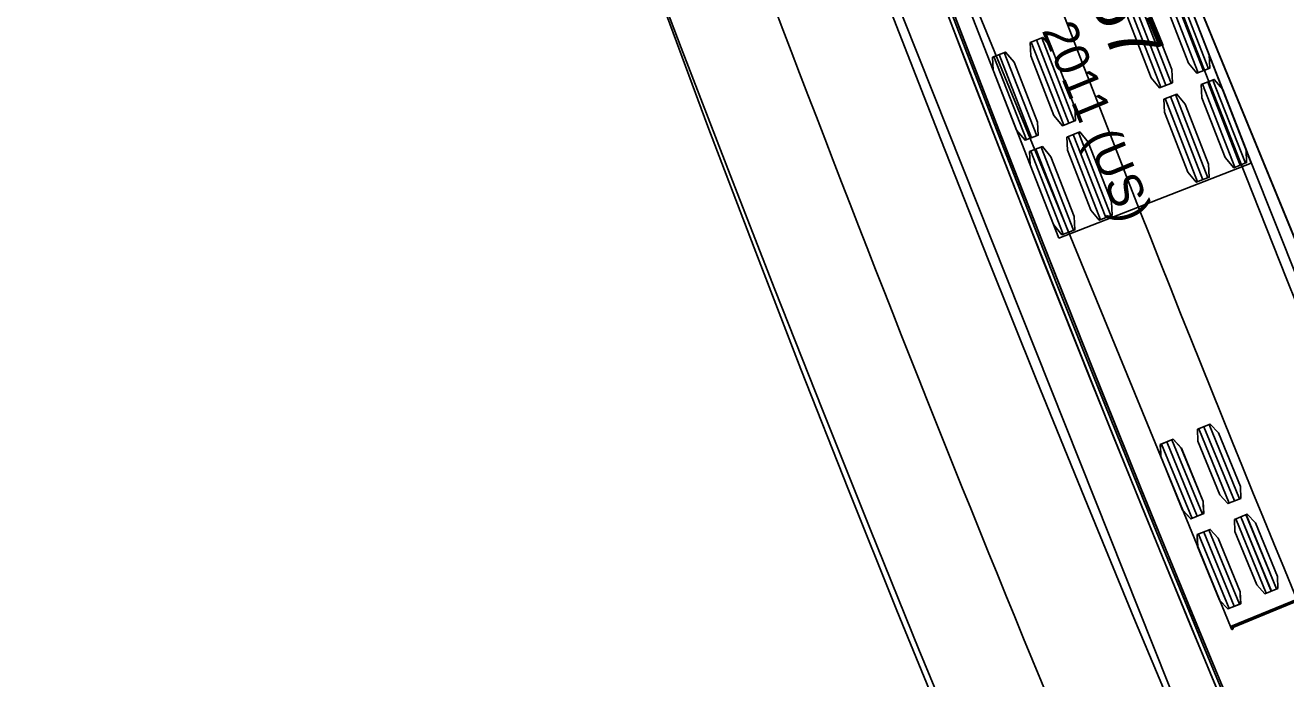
# Model space of a CAD drawing. Extents: x 1639988 to 1641860, y 841974 to 844187.
# Drawn here: x 1640169.8 to 1640221.6, y 844086 to 844112.9 of the extents above; entities that cross this region are included whole.
import ezdxf

# ---------------------------------------------------------------- set-up
doc = ezdxf.new("R2010")
doc.units = 0
for name, color, linetype in [('Scratch_Level_1', 7, 'Continuous'), ('Scratch_Level_2', 7, 'Continuous'), ('Scratch_Level_3', 7, 'Continuous'), ('Scratch_Level_4', 7, 'Continuous'), ('Scratch_Level_5', 7, 'Continuous'), ('Scratch_Level_6', 7, 'Continuous')]:
    doc.layers.add(name, color=color, linetype=linetype)

msp = doc.modelspace()

# ---------------------------------------------------------------- linework, layer by layer
at = {"layer": 'Scratch_Level_1'}
for p, q in [((1640220.202, 844107.217), (1640204.762, 844146.813)), ((1640196.843, 844143.725), (1640212.283, 844104.129)), ((1640216.685, 844114.343), (1640218.017, 844110.927)), ((1640216.899, 844114.426), (1640218.231, 844111.01)), ((1640217.112, 844114.509), (1640218.444, 844111.093)), ((1640215.148, 844113.744), (1640216.48, 844110.327)), ((1640215.361, 844113.827), (1640216.694, 844110.411)), ((1640215.575, 844113.91), (1640216.907, 844110.494)), ((1640211.157, 844112.187), (1640212.489, 844108.771)), ((1640211.371, 844112.271), (1640212.703, 844108.855)), ((1640211.584, 844112.354), (1640212.916, 844108.938)), ((1640209.62, 844111.588), (1640210.952, 844108.172)), ((1640209.834, 844111.671), (1640211.166, 844108.255)), ((1640210.047, 844111.755), (1640211.379, 844108.338)), ((1640218.199, 844110.461), (1640219.531, 844107.045)), ((1640218.412, 844110.544), (1640219.744, 844107.128)), ((1640218.626, 844110.627), (1640219.958, 844107.211)), ((1640216.875, 844109.945), (1640218.207, 844106.529)), ((1640217.089, 844110.028), (1640218.421, 844106.612)), ((1640216.662, 844109.862), (1640217.994, 844106.445)), ((1640212.884, 844108.389), (1640214.217, 844104.973)), ((1640213.098, 844108.472), (1640214.43, 844105.056)), ((1640211.347, 844107.789), (1640212.679, 844104.373)), ((1640211.561, 844107.873), (1640212.893, 844104.456)), ((1640212.671, 844108.305), (1640214.003, 844104.889)), ((1640211.134, 844107.706), (1640212.466, 844104.29)), ((1640212.283, 844104.129), (1640220.202, 844107.217))]:
    msp.add_line(p, q, dxfattribs=at)
for points in [[(1640240.487, 843983.993), (1640239.855, 843986.609), (1640227.577, 844027.488), (1640224.497, 844037.651), (1640222.927, 844042.709), (1640221.325, 844047.747), (1640219.681, 844052.761), (1640217.992, 844057.753), (1640216.257, 844062.717), (1640214.476, 844067.667), (1640212.652, 844072.609), (1640208.555, 844082.348), (1640206.537, 844087.24), (1640204.541, 844092.149), (1640202.565, 844097.075), (1640200.611, 844102.018), (1640198.676, 844106.976), (1640196.761, 844111.949), (1640192.983, 844121.925), (1640185.677, 844141.598), (1640169.789, 844184.508), (1640177.76, 844187.459), (1640177.815, 844187.311), (1640177.815, 844187.311)], [(1640177.815, 844187.311), (1640188.919, 844157.376), (1640192.648, 844147.427), (1640196.411, 844137.497), (1640200.22, 844127.592), (1640204.089, 844117.705), (1640228.263, 844057.033)], [(1640200.563, 844158.427), (1640204.547, 844146.924), (1640204.762, 844146.813), (1640220.203, 844107.235), (1640222.166, 844102.297), (1640224.155, 844097.371), (1640226.171, 844092.456), (1640228.214, 844087.553), (1640230.284, 844082.66)], [(1640220.307, 844082.415), (1640218.24, 844087.364), (1640216.2, 844092.323), (1640214.186, 844097.294), (1640212.199, 844102.274), (1640210.121, 844107.569), (1640208.206, 844112.529), (1640206.319, 844117.491), (1640204.459, 844122.464), (1640202.625, 844127.447), (1640200.818, 844132.44), (1640199.024, 844137.479), (1640196.843, 844143.725), (1640197.043, 844143.873), (1640195.321, 844148.9)]]:
    msp.add_lwpolyline(points, dxfattribs=at)
for points in [[(1640216.632, 844114.322), (1640217.165, 844114.53), (1640217.512, 844114.114), (1640218.471, 844111.655), (1640218.497, 844111.114), (1640217.964, 844110.906), (1640217.617, 844111.322), (1640216.658, 844113.781)], [(1640215.095, 844113.723), (1640215.628, 844113.931), (1640215.975, 844113.515), (1640216.934, 844111.055), (1640216.96, 844110.515), (1640216.427, 844110.307), (1640216.08, 844110.722), (1640215.121, 844113.182)], [(1640211.104, 844112.167), (1640211.637, 844112.375), (1640211.984, 844111.959), (1640212.943, 844109.499), (1640212.969, 844108.958), (1640212.436, 844108.751), (1640212.089, 844109.166), (1640211.13, 844111.626)], [(1640209.567, 844111.567), (1640210.1, 844111.775), (1640210.447, 844111.36), (1640211.406, 844108.9), (1640211.432, 844108.359), (1640210.899, 844108.151), (1640210.552, 844108.567), (1640209.593, 844111.026)], [(1640218.146, 844110.44), (1640218.679, 844110.648), (1640219.026, 844110.232), (1640219.985, 844107.773), (1640220.011, 844107.232), (1640219.478, 844107.024), (1640219.131, 844107.44), (1640218.172, 844109.899)], [(1640216.609, 844109.841), (1640217.142, 844110.049), (1640217.489, 844109.633), (1640218.448, 844107.173), (1640218.474, 844106.633), (1640217.941, 844106.425), (1640217.594, 844106.84), (1640216.635, 844109.3)], [(1640212.618, 844108.285), (1640213.151, 844108.493), (1640213.498, 844108.077), (1640214.457, 844105.617), (1640214.483, 844105.076), (1640213.95, 844104.869), (1640213.603, 844105.284), (1640212.644, 844107.744)], [(1640211.081, 844107.685), (1640211.614, 844107.893), (1640211.961, 844107.478), (1640212.92, 844105.018), (1640212.946, 844104.477), (1640212.413, 844104.269), (1640212.066, 844104.685), (1640211.107, 844107.145)]]:
    msp.add_lwpolyline(points, close=True, dxfattribs=at)
for radius, start, end in [(994, 198.505393, 206.873019), (1005, 200.317507, 203.824551)]:
    msp.add_arc((1641140.378, 844469.766), radius, start, end, dxfattribs=at)
at = {"layer": 'Scratch_Level_2'}
for p, q in [((1640218.252, 844096.387), (1640219.507, 844093.335)), ((1640218.464, 844096.474), (1640219.719, 844093.422)), ((1640218.04, 844096.3), (1640219.295, 844093.248)), ((1640216.514, 844095.673), (1640217.768, 844092.62)), ((1640216.726, 844095.76), (1640217.98, 844092.708)), ((1640216.938, 844095.847), (1640218.192, 844092.795)), ((1640219.985, 844092.774), (1640221.239, 844089.722)), ((1640219.561, 844092.6), (1640220.815, 844089.548)), ((1640219.773, 844092.687), (1640221.027, 844089.635)), ((1640218.034, 844091.973), (1640219.289, 844088.921)), ((1640218.246, 844092.06), (1640219.501, 844089.008)), ((1640218.458, 844092.147), (1640219.713, 844089.095)), ((1640227.208, 844091.408), (1640219.346, 844088.178))]:
    msp.add_line(p, q, dxfattribs=at)
for points in [[(1640240.487, 843983.993), (1640239.855, 843986.609), (1640227.577, 844027.488), (1640224.497, 844037.651), (1640222.927, 844042.709), (1640221.325, 844047.747), (1640219.681, 844052.761), (1640217.992, 844057.753), (1640216.257, 844062.717), (1640214.476, 844067.667), (1640212.652, 844072.609), (1640208.555, 844082.348), (1640206.537, 844087.24), (1640204.541, 844092.149), (1640202.565, 844097.075), (1640200.611, 844102.018), (1640198.676, 844106.976), (1640196.761, 844111.949), (1640192.983, 844121.925), (1640185.677, 844141.598), (1640169.789, 844184.508), (1640177.76, 844187.459), (1640177.811, 844187.321), (1640177.811, 844187.321)], [(1640177.811, 844187.321), (1640188.919, 844157.376), (1640192.648, 844147.427), (1640196.411, 844137.497), (1640200.22, 844127.592), (1640204.089, 844117.705), (1640228.263, 844057.033)], [(1640220.38, 844082.445), (1640218.314, 844087.392), (1640216.154, 844092.648), (1640214.158, 844097.58), (1640212.19, 844102.516), (1640210.249, 844107.464), (1640208.334, 844112.422), (1640206.445, 844117.391), (1640204.582, 844122.37), (1640202.745, 844127.361), (1640200.909, 844132.432), (1640199.257, 844137.07), (1640199.32, 844137.222), (1640197.553, 844142.266), (1640195.83, 844147.27), (1640194.126, 844152.304), (1640192.663, 844156.699), (1640200.197, 844159.388), (1640205.316, 844145.036), (1640206.939, 844140.402), (1640207.119, 844140.301), (1640227.327, 844091.148), (1640229.381, 844086.251), (1640231.462, 844081.368)], [(1640227.214, 844091.335), (1640227.234, 844091.343), (1640227.208, 844091.408), (1640225.054, 844096.65), (1640207.119, 844140.301), (1640203.188, 844138.686), (1640199.257, 844137.07), (1640217.192, 844093.42), (1640219.347, 844088.178), (1640219.374, 844088.113), (1640219.394, 844088.121)], [(1640219.416, 844088.13), (1640219.417, 844088.131), (1640222.779, 844089.512), (1640222.813, 844089.526), (1640222.839, 844089.461), (1640222.841, 844089.461), (1640223.088, 844089.563)]]:
    msp.add_lwpolyline(points, dxfattribs=at)
for points in [[(1640217.988, 844096.278), (1640218.517, 844096.496), (1640218.852, 844096.134), (1640219.755, 844093.936), (1640219.771, 844093.443), (1640219.242, 844093.226), (1640218.907, 844093.588), (1640218.004, 844095.785)], [(1640216.462, 844095.651), (1640216.991, 844095.869), (1640217.326, 844095.507), (1640218.229, 844093.309), (1640218.245, 844092.816), (1640217.716, 844092.599), (1640217.381, 844092.961), (1640216.478, 844095.158)], [(1640219.508, 844092.578), (1640220.037, 844092.796), (1640220.372, 844092.434), (1640221.275, 844090.236), (1640221.291, 844089.743), (1640220.762, 844089.526), (1640220.427, 844089.888), (1640219.524, 844092.086)], [(1640217.982, 844091.951), (1640218.511, 844092.169), (1640218.846, 844091.807), (1640219.749, 844089.609), (1640219.765, 844089.116), (1640219.236, 844088.899), (1640218.901, 844089.261), (1640217.998, 844091.459)]]:
    msp.add_lwpolyline(points, close=True, dxfattribs=at)
msp.add_circle((1640219.418, 844088.094), 0.0266, dxfattribs=at)
for centre, radius, start, end in [((1641140.378, 844469.766), 994, 198.505393, 206.873019), ((1641140.378, 844469.766), 1005, 200.317507, 203.824551), ((1640219.418, 844088.094), 0.0363, 131.4145, 92.5759)]:
    msp.add_arc(centre, radius, start, end, dxfattribs=at)
at = {"layer": 'Scratch_Level_3'}
for p, q in [((1640218.251, 844096.386), (1640219.505, 844093.334)), ((1640218.463, 844096.474), (1640219.717, 844093.421)), ((1640218.039, 844096.299), (1640219.293, 844093.247)), ((1640216.513, 844095.672), (1640217.767, 844092.62)), ((1640216.725, 844095.759), (1640217.979, 844092.707)), ((1640216.936, 844095.847), (1640218.191, 844092.794)), ((1640219.983, 844092.774), (1640221.237, 844089.721)), ((1640219.559, 844092.599), (1640220.813, 844089.547)), ((1640219.771, 844092.687), (1640221.025, 844089.634)), ((1640218.033, 844091.972), (1640219.287, 844088.92)), ((1640218.245, 844092.059), (1640219.499, 844089.007)), ((1640218.457, 844092.147), (1640219.711, 844089.094)), ((1640227.206, 844091.407), (1640219.344, 844088.177))]:
    msp.add_line(p, q, dxfattribs=at)
for points in [[(1640240.487, 843983.993), (1640239.855, 843986.609), (1640227.577, 844027.488), (1640224.497, 844037.651), (1640222.927, 844042.709), (1640221.325, 844047.747), (1640219.681, 844052.761), (1640217.992, 844057.753), (1640216.257, 844062.717), (1640214.476, 844067.667), (1640212.652, 844072.609), (1640208.555, 844082.348), (1640206.537, 844087.24), (1640204.541, 844092.149), (1640202.565, 844097.075), (1640200.611, 844102.018), (1640198.676, 844106.976), (1640196.761, 844111.949), (1640192.983, 844121.925), (1640185.677, 844141.598), (1640169.789, 844184.508), (1640177.76, 844187.459), (1640177.809, 844187.326), (1640177.809, 844187.326)], [(1640177.809, 844187.326), (1640188.919, 844157.376), (1640192.648, 844147.427), (1640196.411, 844137.497), (1640200.22, 844127.592), (1640204.089, 844117.705), (1640228.263, 844057.033)], [(1640219.861, 844083.681), (1640217.802, 844088.63), (1640215.645, 844093.899), (1640213.642, 844098.867), (1640211.667, 844103.843), (1640209.719, 844108.829), (1640207.797, 844113.826), (1640205.902, 844118.835), (1640204.033, 844123.854), (1640202.184, 844128.901), (1640199.257, 844137.071), (1640199.32, 844137.222), (1640197.553, 844142.266), (1640195.83, 844147.27), (1640194.126, 844152.304), (1640192.663, 844156.699), (1640200.197, 844159.388), (1640205.316, 844145.036), (1640206.939, 844140.403), (1640207.119, 844140.301), (1640227.452, 844090.84), (1640229.508, 844085.945)], [(1640227.213, 844091.334), (1640227.232, 844091.342), (1640227.206, 844091.407), (1640225.053, 844096.649), (1640207.119, 844140.301), (1640203.188, 844138.686), (1640199.257, 844137.071), (1640217.19, 844093.419), (1640219.345, 844088.178), (1640219.372, 844088.112), (1640219.392, 844088.12)], [(1640219.414, 844088.129), (1640219.415, 844088.13), (1640222.778, 844089.512), (1640222.811, 844089.525), (1640222.837, 844089.46), (1640222.839, 844089.46), (1640223.086, 844089.562)]]:
    msp.add_lwpolyline(points, dxfattribs=at)
for points in [[(1640217.986, 844096.278), (1640218.515, 844096.495), (1640218.85, 844096.133), (1640219.753, 844093.936), (1640219.769, 844093.443), (1640219.24, 844093.225), (1640218.905, 844093.587), (1640218.002, 844095.785)], [(1640216.46, 844095.651), (1640216.989, 844095.868), (1640217.324, 844095.506), (1640218.227, 844093.308), (1640218.243, 844092.816), (1640217.714, 844092.598), (1640217.379, 844092.96), (1640216.476, 844095.158)], [(1640219.506, 844092.578), (1640220.035, 844092.795), (1640220.37, 844092.433), (1640221.273, 844090.236), (1640221.289, 844089.743), (1640220.76, 844089.525), (1640220.425, 844089.887), (1640219.522, 844092.085)], [(1640217.98, 844091.951), (1640218.509, 844092.168), (1640218.844, 844091.806), (1640219.747, 844089.609), (1640219.763, 844089.116), (1640219.234, 844088.898), (1640218.899, 844089.26), (1640217.996, 844091.458)]]:
    msp.add_lwpolyline(points, close=True, dxfattribs=at)
msp.add_circle((1640219.416, 844088.093), 0.0266, dxfattribs=at)
for centre, radius, start, end in [((1641140.378, 844469.766), 994, 198.505393, 206.873019), ((1641140.378, 844469.766), 1005, 200.317507, 203.824551), ((1640219.416, 844088.093), 0.0363, 131.4122, 92.5735)]:
    msp.add_arc(centre, radius, start, end, dxfattribs=at)
at = {"layer": 'Scratch_Level_4'}
for points in [[(1640199.38, 844162.307), (1640212.128, 844127.237), (1640213.982, 844122.255), (1640215.862, 844117.284), (1640217.769, 844112.323), (1640219.703, 844107.372), (1640221.663, 844102.432), (1640223.649, 844097.502), (1640225.662, 844092.583), (1640227.702, 844087.676), (1640229.768, 844082.779)], [(1640207.65, 844083.889), (1640205.634, 844088.831), (1640203.645, 844093.787), (1640201.686, 844098.755), (1640199.758, 844103.733), (1640197.861, 844108.723), (1640182.463, 844150.279), (1640190.434, 844153.23), (1640190.54, 844152.943), (1640190.54, 844152.943)], [(1640190.54, 844152.943), (1640197.954, 844132.962), (1640201.698, 844123.028), (1640205.503, 844113.126), (1640207.434, 844108.188), (1640209.385, 844103.259), (1640211.358, 844098.34), (1640213.353, 844093.431), (1640215.372, 844088.529), (1640219.496, 844078.72)], [(1640219.769, 844083.264), (1640217.707, 844088.215), (1640215.671, 844093.176), (1640213.661, 844098.149), (1640211.678, 844103.133), (1640209.723, 844108.127), (1640207.793, 844113.131), (1640205.891, 844118.146), (1640204.016, 844123.17), (1640202.17, 844128.2), (1640200.243, 844133.54), (1640198.46, 844138.567), (1640196.705, 844143.604), (1640194.97, 844148.666)]]:
    msp.add_lwpolyline(points, dxfattribs=at)
for radius, start, end in [(994, 198.505393, 206.873019), (1005, 200.317507, 203.824551)]:
    msp.add_arc((1641140.378, 844469.766), radius, start, end, dxfattribs=at)
at = {"layer": 'Scratch_Level_5'}
for points in [[(1640199.38, 844162.307), (1640212.128, 844127.237), (1640213.982, 844122.255), (1640215.862, 844117.284), (1640217.769, 844112.323), (1640219.703, 844107.372), (1640221.663, 844102.432), (1640223.649, 844097.502), (1640225.662, 844092.583), (1640227.702, 844087.676), (1640229.768, 844082.779)], [(1640207.65, 844083.889), (1640205.634, 844088.831), (1640203.645, 844093.787), (1640201.686, 844098.755), (1640199.758, 844103.733), (1640197.861, 844108.723), (1640182.463, 844150.279), (1640190.434, 844153.23), (1640190.528, 844152.975), (1640190.528, 844152.975)], [(1640190.528, 844152.975), (1640197.954, 844132.962), (1640201.698, 844123.028), (1640205.503, 844113.126), (1640207.434, 844108.188), (1640209.385, 844103.259), (1640211.358, 844098.34), (1640213.353, 844093.431), (1640215.372, 844088.529), (1640219.496, 844078.72)], [(1640220.68, 844081.101), (1640218.606, 844086.047), (1640216.558, 844091.004), (1640214.537, 844095.972), (1640212.543, 844100.951), (1640210.575, 844105.941), (1640208.634, 844110.94), (1640206.72, 844115.951), (1640204.833, 844120.971), (1640202.974, 844125.999), (1640201.032, 844131.341), (1640199.237, 844136.367), (1640197.469, 844141.399), (1640195.728, 844146.442), (1640194.003, 844151.528)]]:
    msp.add_lwpolyline(points, dxfattribs=at)
for radius, start, end in [(994, 198.505393, 206.873019), (1005, 200.317507, 203.824551)]:
    msp.add_arc((1641140.378, 844469.766), radius, start, end, dxfattribs=at)
at = {"layer": 'Scratch_Level_6'}
for points in [[(1640199.38, 844162.307), (1640212.128, 844127.237), (1640213.982, 844122.255), (1640215.862, 844117.284), (1640217.769, 844112.323), (1640219.703, 844107.372), (1640221.663, 844102.432), (1640223.649, 844097.502), (1640225.662, 844092.583), (1640227.702, 844087.676), (1640229.768, 844082.779)], [(1640207.65, 844083.889), (1640205.634, 844088.831), (1640203.645, 844093.787), (1640201.686, 844098.755), (1640199.758, 844103.733), (1640197.861, 844108.723), (1640182.463, 844150.279), (1640190.434, 844153.23), (1640190.518, 844153.001), (1640190.518, 844153.001)], [(1640190.518, 844153.001), (1640197.954, 844132.962), (1640201.698, 844123.028), (1640205.503, 844113.126), (1640207.434, 844108.188), (1640209.385, 844103.259), (1640211.358, 844098.34), (1640213.353, 844093.431), (1640215.372, 844088.529), (1640219.496, 844078.72)], [(1640220.68, 844081.101), (1640218.606, 844086.047), (1640216.558, 844091.004), (1640214.537, 844095.972), (1640212.543, 844100.951), (1640210.575, 844105.941), (1640208.634, 844110.94), (1640206.72, 844115.951), (1640204.833, 844120.971), (1640202.974, 844125.999), (1640201.032, 844131.341), (1640199.237, 844136.367), (1640197.469, 844141.399), (1640195.728, 844146.442), (1640194.003, 844151.528)]]:
    msp.add_lwpolyline(points, dxfattribs=at)
for radius, start, end in [(994, 198.505393, 206.873019), (1005, 200.317507, 203.824551)]:
    msp.add_arc((1641140.378, 844469.766), radius, start, end, dxfattribs=at)

# ---------------------------------------------------------------- texts
at = {"layer": 'Scratch_Level_2'}
for s, height, p in [('AASHTO 2011 (US)', 1.41667, (1640208.412, 844120.36)), ('WB-67', 2.125, (1640211.398, 844119.153))]:
    msp.add_text(s, height=height, rotation=292.3371, dxfattribs=at).set_placement(p)
at = {"layer": 'Scratch_Level_3'}
for s, height, p in [('AASHTO 2011 (US)', 1.41667, (1640208.412, 844120.36)), ('WB-67', 2.125, (1640211.397, 844119.152))]:
    msp.add_text(s, height=height, rotation=292.3347, dxfattribs=at).set_placement(p)

doc.saveas('drawing.dxf')
